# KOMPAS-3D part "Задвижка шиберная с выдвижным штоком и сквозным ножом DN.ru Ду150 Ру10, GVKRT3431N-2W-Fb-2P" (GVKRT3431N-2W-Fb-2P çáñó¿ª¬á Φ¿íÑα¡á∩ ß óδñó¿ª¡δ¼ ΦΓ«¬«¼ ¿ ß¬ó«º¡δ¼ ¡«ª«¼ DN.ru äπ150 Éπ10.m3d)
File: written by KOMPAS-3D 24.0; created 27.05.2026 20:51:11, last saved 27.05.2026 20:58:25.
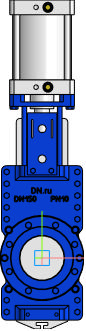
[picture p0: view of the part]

Document properties: Автор: DN.ru; Полное имя файла: C:\Работа\ГОТОВЫЕ ИСХОДНИКИ\GVKRT3431N-2W-Fb-2P Задвижка шиберная со сквозным ножом DN.ru Ду100-250 Ру16\DN150\GVKRT3431N-2W-Fb-2P Задвижка шиберная с выдвижным штоком и сквозным ножом DN.ru Ду150 Ру10.m3d

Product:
- Part/product: Задвижка шиберная с выдвижным штоком и сквозным ножом DN.ru Ду150 Ру10  | designation GVKRT3431N-2W-Fb-2P
    Масса: 37
    Раздел спецификации: Прочие изделия
    Примечание: D040-08531

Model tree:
1. Операция без истории:1

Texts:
  GVKRT3431N-2W-Fb-2P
